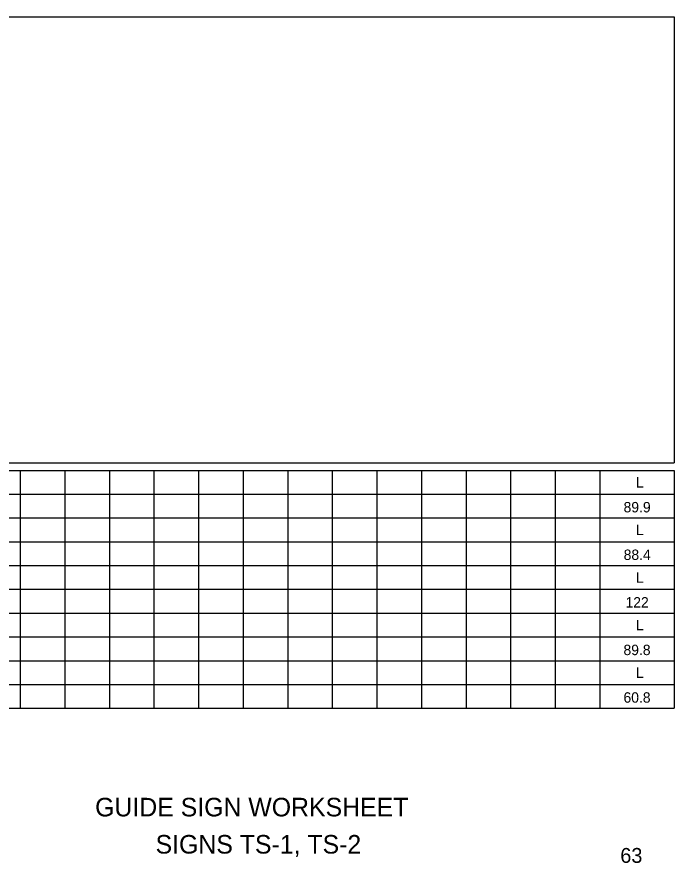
# Model space of a CAD drawing. Extents: x 10268312 to 10268471, y 2141099 to 2141204.
# Drawn here: x 10268426.8 to 10268471, y 2141101.8 to 2141158.7 of the extents above; entities that cross this region are included whole.
import ezdxf

# ---------------------------------------------------------------- set-up
doc = ezdxf.new("R2010")
doc.units = 0
for name, color, linetype in [('SumBoxLines_dp', 7, 'Continuous'), ('SumBoxLinesMin_dp', 7, 'Continuous'), ('TextLabel', 7, 'Continuous'), ('TextMisc', 7, 'Continuous'), ('TextShtNo', 7, 'Continuous')]:
    doc.layers.add(name, color=color, linetype=linetype)

msp = doc.modelspace()

# ---------------------------------------------------------------- linework, layer by layer
at = {"layer": 'SumBoxLines_dp'}
for p, q in [((10268341.73, 2141158.728), (10268470.98, 2141158.728)), ((10268470.98, 2141158.728), (10268470.98, 2141128.728)), ((10268341.73, 2141128.728), (10268470.98, 2141128.728)), ((10268318.48, 2141128.228), (10268470.98, 2141128.228)), ((10268426.98, 2141128.228), (10268426.98, 2141112.228)), ((10268429.98, 2141128.228), (10268429.98, 2141112.228)), ((10268432.98, 2141128.228), (10268432.98, 2141112.228)), ((10268435.98, 2141128.228), (10268435.98, 2141112.228)), ((10268438.98, 2141128.228), (10268438.98, 2141112.228)), ((10268441.98, 2141128.228), (10268441.98, 2141112.228)), ((10268444.98, 2141128.228), (10268444.98, 2141112.228)), ((10268447.98, 2141128.228), (10268447.98, 2141112.228)), ((10268450.98, 2141128.228), (10268450.98, 2141112.228)), ((10268453.98, 2141128.228), (10268453.98, 2141112.228)), ((10268456.98, 2141128.228), (10268456.98, 2141112.228)), ((10268459.98, 2141128.228), (10268459.98, 2141112.228)), ((10268462.98, 2141128.228), (10268462.98, 2141112.228)), ((10268465.98, 2141128.228), (10268465.98, 2141112.228)), ((10268470.98, 2141128.228), (10268470.98, 2141112.228)), ((10268318.48, 2141125.028), (10268470.98, 2141125.028)), ((10268318.48, 2141121.828), (10268470.98, 2141121.828)), ((10268318.48, 2141118.628), (10268470.98, 2141118.628)), ((10268318.48, 2141115.428), (10268470.98, 2141115.428)), ((10268318.48, 2141112.228), (10268470.98, 2141112.228))]:
    msp.add_line(p, q, dxfattribs=at)
at = {"layer": 'SumBoxLinesMin_dp'}
for p, q in [((10268318.48, 2141126.628), (10268470.98, 2141126.628)), ((10268318.48, 2141123.428), (10268470.98, 2141123.428)), ((10268318.48, 2141120.228), (10268470.98, 2141120.228)), ((10268318.48, 2141117.028), (10268470.98, 2141117.028)), ((10268318.48, 2141113.828), (10268470.98, 2141113.828))]:
    msp.add_line(p, q, dxfattribs=at)

# ---------------------------------------------------------------- texts
at = {"layer": 'TextLabel'}
for s, p in [('L', (10268468.411, 2141127.073)), ('89.9', (10268467.582, 2141125.403)), ('L', (10268468.411, 2141123.873)), ('88.4', (10268467.588, 2141122.203)), ('L', (10268468.411, 2141120.673)), ('122', (10268467.712, 2141119.003)), ('L', (10268468.411, 2141117.473)), ('89.8', (10268467.576, 2141115.803)), ('L', (10268468.411, 2141114.273)), ('60.8', (10268467.576, 2141112.603))]:
    msp.add_text(s, height=0.7, dxfattribs=at).set_placement(p)
at = {"layer": 'TextMisc'}
for s, p in [('  GUIDE SIGN WORKSHEET  ', (10268431.091, 2141104.954)), ('    SIGNS TS-1, TS-2    ', (10268434.231, 2141102.454))]:
    msp.add_text(s, height=1.25, rotation=360, dxfattribs=at).set_placement(p)
at = {"layer": 'TextShtNo'}
msp.add_text('63', height=1, rotation=360, dxfattribs=at).set_placement((10268467.361, 2141101.829))

doc.saveas('drawing.dxf')
